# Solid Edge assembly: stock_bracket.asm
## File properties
Author: Robert a Rhodes jr
Template: Normal.asm
Last saved by: Cadcim
Revision: 26
Application: Solid Edge
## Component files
adjusting_screw_guide.par
adjusting_nut_handle.par
stock_support_roller.par
Stock_support_base.par
thrust_bearing.par
adjusting_screw_nut.par
support_adjusting_screw.par
support_roller_bracket.par
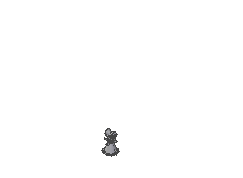
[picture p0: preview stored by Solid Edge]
